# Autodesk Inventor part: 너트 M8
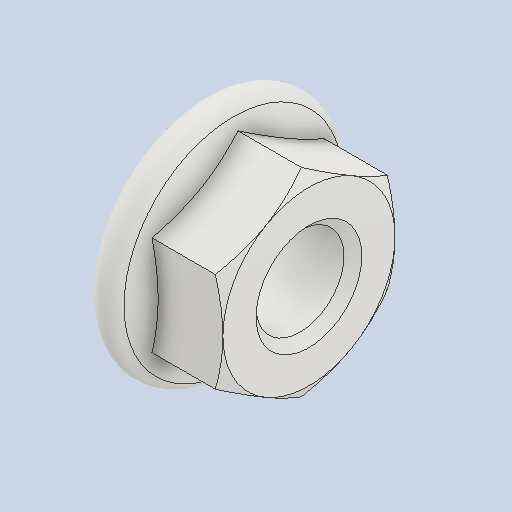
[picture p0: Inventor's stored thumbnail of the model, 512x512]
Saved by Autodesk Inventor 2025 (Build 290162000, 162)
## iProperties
Created: 2025-08
Part Number: 너트 M8
Material: 스테인리스강
Description: 플랜지붙이 6각 너트 - 일반 스레드
Document SubType Name: Modeling
Designer: infra02
Density: 8 g/cm^3
Appearance: 기본값
Author: jhkim
Sending System: Autodesk Inventor 2026
Preprocessor: ST-DEVELOPER v20.1
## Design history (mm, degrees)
feature "Solid1"
node "솔리드1"
